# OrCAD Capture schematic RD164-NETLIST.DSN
size A3
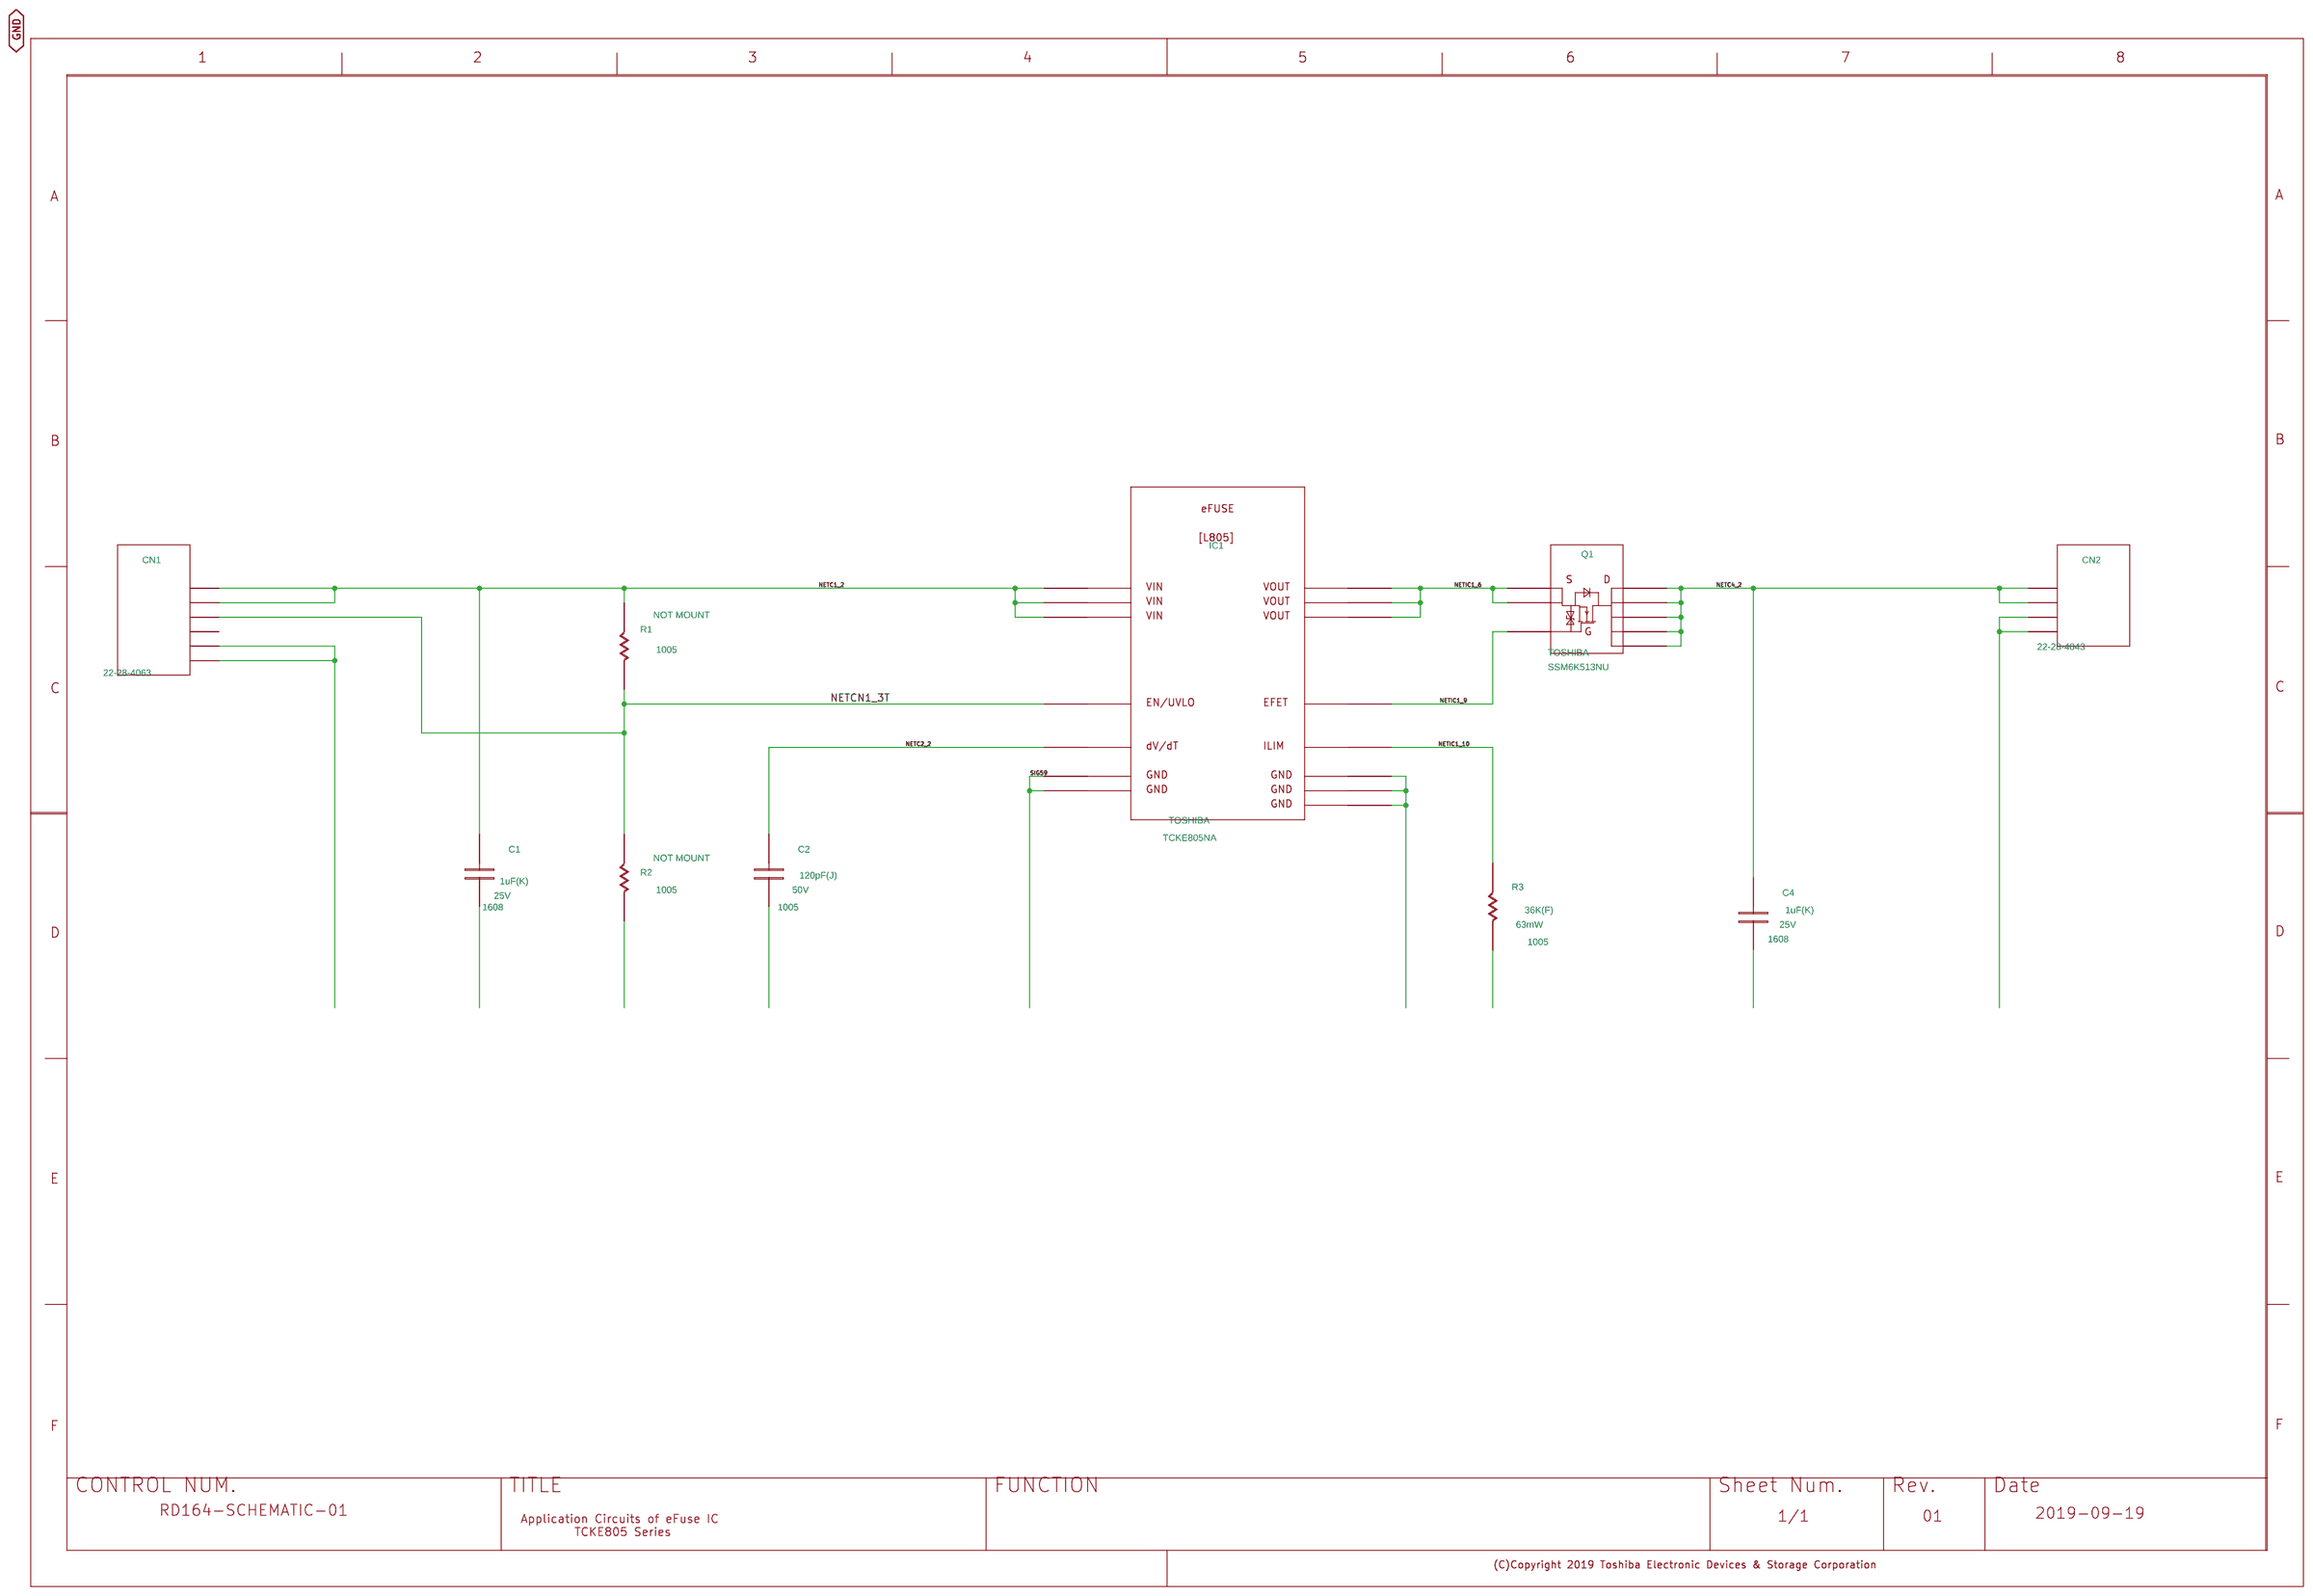
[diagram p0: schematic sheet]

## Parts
C1  C
C2  C
C4  C
CN1  22-28-4063
CN2  22-28-4043
IC1  TCKE805
Q1  SSM6K513
R1  R
R2  R
R3  R
U?#1  WAKU_DEF100

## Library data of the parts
C1 = C: CDBNAME: GDM030001341; COMPONENTNAME: GDM030001341_package; COMPONENTTYPE: 4; FUNCTION: GDM030001341; GCOUNT: 1; MAXGCOUNT: 1; PARTNAME: TAIYO_YUDEN_1608_1; SIZECODESMD: 1608; VAL1: 1uF(K); VAL2: 25V; VAL3: TMK107BJ105KA-T
C2 = C: CDBNAME: K0300575; COMPONENTNAME: K0300575_package; COMPONENTTYPE: 4; FUNCTION: K0300575; GCOUNT: 1; MAXGCOUNT: 1; PARTNAME: C1005_MURATA; SIZECODESMD: 1005; VAL1: 120pF(J); VAL2: 50V; VAL3: UMK105SL121JV-F
C4 = C: CDBNAME: GDM030001341; COMPONENTNAME: GDM030001341_package; COMPONENTTYPE: 4; FUNCTION: GDM030001341; GCOUNT: 1; MAXGCOUNT: 1; PARTNAME: TAIYO_YUDEN_1608; SIZECODESMD: 1608; VAL1: 1uF(K); VAL2: 25V; VAL3: TMK107BJ105KA-T
CN1 = 22-28-4063: COMPONENTTYPE: 4; PARTNAME: 2_54_6
CN2 = 22-28-4043: COMPONENTTYPE: 4; PARTNAME: 2_54_4
IC1 = TCKE805: COMPONENTTYPE: 4; PARTNAME: WSON10B; USERCOMPTEXT3: TOSHIBA; VAL1: TCKE805NA; VAL3: TCKE805NA
Q1 = SSM6K513: COMPONENTTYPE: 4; PARTNAME: SSM6K513NU; USERCOMPTEXT3: TOSHIBA; VAL1: SSM6K513NU; VAL3: SSM6K513NU
R1 = R: CDBNAME: GAS010000128; COMPONENTNAME: GAS010000128_package; COMPONENTTYPE: 4; FUNCTION: GAS010000128; GCOUNT: 1; MAXGCOUNT: 1; NOTMOUNT: NOT MOUNT; PARTNAME: R1005_PANA_2; SIZECODESMD: 1005; VAL1: 0(X); VAL2: 0W; VAL3: RK73Z1ETTP@@
R2 = R: CDBNAME: GAS010000128; COMPONENTNAME: GAS010000128_package; COMPONENTTYPE: 4; FUNCTION: GAS010000128; GCOUNT: 1; MAXGCOUNT: 1; NOTMOUNT: NOT MOUNT; PARTNAME: R1005_PANA_1; SIZECODESMD: 1005; VAL1: 0(X); VAL2: 0W; VAL3: RK73Z1ETTP@@
R3 = R: CDBNAME: G36010118220; COMPONENTNAME: G36010118220_package; COMPONENTTYPE: 4; FUNCTION: G36010118220; GCOUNT: 1; MAXGCOUNT: 1; PARTNAME: R1005_PANA; SIZECODESMD: 1005; VAL1: 36K(F); VAL2: 63mW; VAL3: ERJ2RKF3602X
U?#1 = WAKU_DEF100: COMPONENTTYPE: 2; DATE: 2019-09-19; DRAWINGNUMBER: RD164-SCHEMATIC-01; REVISION: 01; SHEETNUMBER: 1/1; TITLE: Application Circuits of eFuse IC / TCKE805 Series; UPDATEDATE: 2019/09/24; UPDATETIME: 17:05:09; UPDATEUSER: t5459927

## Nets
GND: C1.1 C2.1 C4.1 CN1.5T CN1.6T CN2.3T CN2.4T IC1.EP IC1.EP_1 IC1.EP_2 IC1.EP_3 IC1.EP_4 R2.1 R3.1
NETC1_2: C1.2 CN1.1T CN1.2T IC1.3 IC1.4 IC1.5 R1.2
NETC2_2: C2.2 IC1.1
NETC4_2: C4.2 CN2.1T CN2.2T Q1.D Q1.D_1 Q1.D_2 Q1.D_3 Q1.D_4
NETCN1_3T: CN1.3T IC1.2 R1.1 R2.2
NETIC1_6: IC1.6 IC1.7 IC1.8 Q1.S Q1.S_1
NETIC1_9: IC1.9 Q1.G
NETIC1_10: IC1.10 R3.2

Not connected (* = marked no-connect by the designer): CN1 4T
